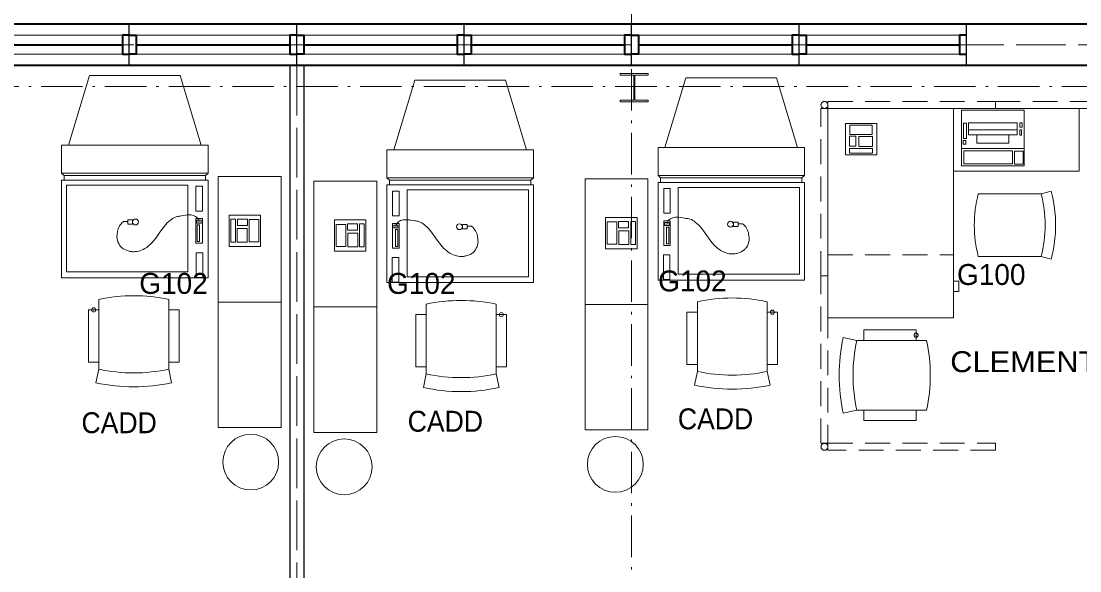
# Model space of a CAD drawing. Extents: x -118748 to -117136, y -118748 to -117596.
# Drawn here: x -118046.3 to -117803.5, y -118079.9 to -117953.8 of the extents above; entities that cross this region are included whole.
import ezdxf
from ezdxf.enums import TextEntityAlignment as Align

# ---------------------------------------------------------------- set-up
doc = ezdxf.new("R2010")
doc.units = 0
doc.header["$LTSCALE"] = 1.9
doc.header["$PDMODE"] = 32
doc.header["$PDSIZE"] = 0.95
for name, pattern in [('DOT_DASHED', [7.7, 5, -1.2, 0.3, -1.2]), ('LONG_DASHED', [7.5, 6, -1.5]), ('MEDIUM_DASHED', [4.5, 3, -1.5])]:
    doc.linetypes.add(name, pattern=pattern)
for name, color, linetype, lineweight in [('10', 7, 'DOT_DASHED', 13), ('12', 7, 'Continuous', 13), ('15', 7, 'Continuous', 13), ('16', 7, 'Continuous', 13), ('20', 7, 'MEDIUM_DASHED', 13), ('23', 7, 'Continuous', 25), ('3', 7, 'Continuous', 35), ('30', 7, 'Continuous', 13), ('4', 7, 'Continuous', 35), ('5', 7, 'Continuous', 13), ('6', 7, 'Continuous', 13), ('60', 7, 'LONG_DASHED', 13), ('9', 7, 'Continuous', 35)]:
    doc.layers.add(name, color=color, linetype=linetype, lineweight=lineweight)
doc.layers.add('53', color=7, linetype='Continuous')

msp = doc.modelspace()

# ---------------------------------------------------------------- linework, layer by layer
at = {"layer": '10'}
for p, q in [((-117906.321, -117628.339), (-117906.321, -118698.41)), ((-118641.571, -117968.81), (-117285.521, -117968.81))]:
    msp.add_line(p, q, dxfattribs=at)
at = {"layer": '12'}
msp.add_lwpolyline([(-117908.916, -117972.298), (-117902.5, -117972.298), (-117902.5, -117971.902), (-117905.584, -117971.902), (-117905.584, -117966.198), (-117902.5, -117966.198), (-117902.5, -117965.802), (-117908.916, -117965.802), (-117908.916, -117966.198), (-117905.832, -117966.198), (-117905.832, -117971.902), (-117908.916, -117971.902)], close=True, dxfattribs=at)
at = {"layer": '15', "lineweight": 25}
for p, q in [((-118021.521, -117964.01), (-118021.521, -117954.41)), ((-118021.521, -117964.01), (-118021.521, -117954.41)), ((-117983.121, -117964.01), (-117983.121, -117954.41)), ((-117983.121, -117964.01), (-117983.121, -117954.41)), ((-117944.721, -117964.01), (-117944.721, -117954.41)), ((-117944.721, -117964.01), (-117944.721, -117954.41)), ((-117906.321, -117964.01), (-117906.321, -117954.41)), ((-117906.321, -117964.01), (-117906.321, -117954.41)), ((-117867.921, -117964.01), (-117867.921, -117954.41)), ((-117867.921, -117964.01), (-117867.921, -117954.41)), ((-117829.521, -117964.01), (-117829.521, -117954.41)), ((-117459.921, -117954.41), (-117829.521, -117954.41)), ((-117469.521, -117964.01), (-117829.521, -117964.01))]:
    msp.add_line(p, q, dxfattribs=at)
at = {"layer": '15'}
for p, q in [((-117826.798, -117993.398), (-117812.398, -117993.398)), ((-117812.398, -117993.398), (-117810.076, -117992.791)), ((-117812.398, -118007.798), (-117826.798, -118007.798)), ((-117812.398, -118007.798), (-117810.076, -118008.404)), ((-118028.49, -118017.64), (-118028.49, -118033.64)), ((-118012.49, -118017.64), (-118012.49, -118033.64)), ((-117953.407, -118018.726), (-117953.407, -118034.726)), ((-117937.407, -118018.726), (-117937.407, -118034.726)), ((-117891.231, -118018.16), (-117891.231, -118034.16)), ((-117875.231, -118018.16), (-117875.231, -118034.16)), ((-118030.89, -118020.04), (-118030.89, -118032.04)), ((-118028.49, -118020.04), (-118030.89, -118020.04)), ((-118028.49, -118020.04), (-118028.49, -118032.04)), ((-118012.49, -118020.04), (-118012.49, -118032.04)), ((-118010.09, -118020.04), (-118012.49, -118020.04)), ((-118010.09, -118020.04), (-118010.09, -118032.04)), ((-117955.807, -118021.126), (-117955.807, -118033.126)), ((-117955.807, -118021.126), (-117953.407, -118021.126)), ((-117953.407, -118021.126), (-117953.407, -118033.126)), ((-117937.407, -118021.126), (-117937.407, -118033.126)), ((-117937.407, -118021.126), (-117935.007, -118021.126)), ((-117935.007, -118021.126), (-117935.007, -118033.126)), ((-117893.631, -118020.56), (-117893.631, -118032.56)), ((-117893.631, -118020.56), (-117891.231, -118020.56)), ((-117891.231, -118020.56), (-117891.231, -118032.56)), ((-117875.231, -118020.56), (-117875.231, -118032.56)), ((-117875.231, -118020.56), (-117872.831, -118020.56)), ((-117872.831, -118020.56), (-117872.831, -118032.56)), ((-117841.071, -118024.64), (-117853.071, -118024.64)), ((-117853.071, -118024.64), (-117853.071, -118027.04)), ((-117841.071, -118027.04), (-117841.071, -118024.64)), ((-117854.671, -118027.04), (-117857.799, -118026.364)), ((-117838.671, -118027.04), (-117854.671, -118027.04)), ((-117841.071, -118027.04), (-117853.071, -118027.04)), ((-118030.89, -118032.04), (-118028.49, -118032.04)), ((-118028.49, -118033.64), (-118029.166, -118036.768)), ((-118012.49, -118032.04), (-118010.09, -118032.04)), ((-118012.49, -118033.64), (-118011.814, -118036.768)), ((-117953.407, -118033.126), (-117955.807, -118033.126)), ((-117935.007, -118033.126), (-117937.407, -118033.126)), ((-117891.231, -118032.56), (-117893.631, -118032.56)), ((-117872.831, -118032.56), (-117875.231, -118032.56)), ((-117953.407, -118034.726), (-117954.084, -118037.853)), ((-117937.407, -118034.726), (-117936.731, -118037.853)), ((-117891.231, -118034.16), (-117891.907, -118037.288)), ((-117875.231, -118034.16), (-117874.555, -118037.288)), ((-117854.671, -118043.04), (-117857.799, -118043.716)), ((-117838.671, -118043.04), (-117854.671, -118043.04)), ((-117841.071, -118043.04), (-117853.071, -118043.04)), ((-117853.071, -118043.04), (-117853.071, -118045.44)), ((-117841.071, -118045.44), (-117841.071, -118043.04)), ((-117841.071, -118045.44), (-117853.071, -118045.44))]:
    msp.add_line(p, q, dxfattribs=at)
for points in [[(-117861.285, -118021.839), (-117832.485, -118021.839), (-117832.485, -117973.839), (-117861.285, -117973.839)], [(-117832.485, -117988.239), (-117803.685, -117988.239), (-117803.685, -117973.839), (-117832.485, -117973.839)], [(-118001.13, -117989.452), (-118001.13, -118018.252), (-117986.73, -118018.252), (-117986.73, -117989.452)], [(-117964.767, -117990.537), (-117964.767, -118019.337), (-117979.167, -118019.337), (-117979.167, -117990.537)], [(-117902.59, -117989.972), (-117902.59, -118018.772), (-117916.99, -118018.772), (-117916.99, -117989.972)], [(-118001.13, -118018.252), (-118001.13, -118047.052), (-117986.73, -118047.052), (-117986.73, -118018.252)], [(-117902.59, -118018.772), (-117902.59, -118047.572), (-117916.99, -118047.572), (-117916.99, -118018.772)], [(-117964.767, -118019.337), (-117964.767, -118048.137), (-117979.167, -118048.137), (-117979.167, -118019.337)]]:
    msp.add_lwpolyline(points, close=True, dxfattribs=at)
for centre, radius, start, end in [((-117799.248, -118000.597), 28.475, 165.35367, 194.64632), ((-117839.948, -118000.597), 28.475, 345.35367, 14.64632), ((-117839.948, -118000.597), 30.875, 345.35367, 14.64632), ((-118020.49, -118054.649), 37.863, 77.80217, 102.19783), ((-117945.407, -118055.734), 37.863, 77.80217, 102.19782), ((-117883.231, -118055.169), 37.863, 77.80217, 102.19782), ((-117817.663, -118035.04), 41.063, 167.80217, 192.19782), ((-117817.663, -118035.04), 37.863, 167.80217, 192.19782), ((-117817.663, -118035.04), 37.863, 167.80217, 192.19782), ((-117875.679, -118035.04), 37.863, 347.80217, 12.19783), ((-118020.49, -117996.632), 37.863, 257.80217, 282.19783), ((-118020.49, -117996.632), 37.863, 257.80217, 282.19783), ((-117945.407, -117997.717), 37.863, 257.80217, 282.19783), ((-117945.407, -117997.717), 37.863, 257.80217, 282.19783), ((-117883.231, -117997.152), 37.863, 257.80217, 282.19783), ((-117883.231, -117997.152), 37.863, 257.80217, 282.19783), ((-118020.49, -117996.632), 41.063, 257.80217, 282.19783), ((-117945.407, -117997.717), 41.063, 257.80217, 282.19783), ((-117883.231, -117997.152), 41.063, 257.80217, 282.19783)]:
    msp.add_arc(centre, radius, start, end, dxfattribs=at)
for p in [(-118029.69, -118020.04), (-117936.207, -118021.126), (-117874.031, -118020.56), (-117841.071, -118025.84)]:
    msp.add_point(p, dxfattribs=at)
at = {"layer": '16'}
for p, q in [((-118059.921, -117954.41), (-118021.521, -117954.41)), ((-118021.521, -117954.41), (-117983.121, -117954.41)), ((-117983.121, -117954.41), (-117944.721, -117954.41)), ((-117944.721, -117954.41), (-117906.321, -117954.41)), ((-117906.321, -117954.41), (-117867.921, -117954.41)), ((-117867.921, -117954.41), (-117829.521, -117954.41)), ((-118058.321, -117957.027), (-118023.121, -117957.027)), ((-118019.921, -117957.027), (-117984.721, -117957.027)), ((-117981.521, -117957.027), (-117946.321, -117957.027)), ((-117943.121, -117957.027), (-117907.921, -117957.027)), ((-117904.721, -117957.027), (-117869.521, -117957.027)), ((-117866.321, -117957.027), (-117831.121, -117957.027)), ((-118023.121, -117961.391), (-118058.321, -117961.391)), ((-117984.721, -117961.391), (-118019.921, -117961.391)), ((-117946.321, -117961.391), (-117981.521, -117961.391)), ((-117907.921, -117961.391), (-117943.121, -117961.391)), ((-117869.521, -117961.391), (-117904.721, -117961.391)), ((-117831.121, -117961.391), (-117866.321, -117961.391)), ((-118021.521, -117964.01), (-118059.921, -117964.01)), ((-117983.121, -117964.01), (-118021.521, -117964.01)), ((-117944.721, -117964.01), (-117983.121, -117964.01)), ((-117906.321, -117964.01), (-117944.721, -117964.01)), ((-117867.921, -117964.01), (-117906.321, -117964.01)), ((-117829.521, -117964.01), (-117867.921, -117964.01)), ((-118035.457, -117982.266), (-118030.657, -117966.266)), ((-118030.657, -117966.266), (-118009.857, -117966.266)), ((-118005.057, -117982.266), (-118009.857, -117966.266)), ((-117960.84, -117983.351), (-117956.04, -117967.351)), ((-117935.24, -117967.351), (-117956.04, -117967.351)), ((-117930.44, -117983.351), (-117935.24, -117967.351)), ((-117898.664, -117982.786), (-117893.864, -117966.786)), ((-117873.064, -117966.786), (-117893.864, -117966.786)), ((-117868.264, -117982.786), (-117873.064, -117966.786)), ((-117830.687, -117983.025), (-117816.287, -117983.025)), ((-118036.474, -117989.2), (-118037.057, -117988.666)), ((-118004.021, -117989.2), (-118003.457, -117988.666)), ((-117961.876, -117990.285), (-117962.44, -117989.751)), ((-117929.423, -117990.285), (-117928.84, -117989.751)), ((-117899.699, -117989.72), (-117900.264, -117989.186)), ((-117867.246, -117989.72), (-117866.664, -117989.186))]:
    msp.add_line(p, q, dxfattribs=at)
at = {"layer": '16', "lineweight": 35}
for p, q in [((-118058.321, -117959.209), (-118023.121, -117959.209)), ((-118019.921, -117959.209), (-117984.721, -117959.209)), ((-117981.521, -117959.209), (-117946.321, -117959.209)), ((-117943.121, -117959.209), (-117907.921, -117959.209)), ((-117904.721, -117959.209), (-117869.521, -117959.209)), ((-117866.321, -117959.209), (-117831.121, -117959.209))]:
    msp.add_line(p, q, dxfattribs=at)
for points in [[(-118021.521, -117957.027), (-118023.121, -117957.027), (-118023.121, -117961.391), (-118021.521, -117961.391)], [(-118021.521, -117957.027), (-118019.921, -117957.027), (-118019.921, -117961.391), (-118021.521, -117961.391)], [(-117983.121, -117957.027), (-117984.721, -117957.027), (-117984.721, -117961.391), (-117983.121, -117961.391)], [(-117983.121, -117957.027), (-117981.521, -117957.027), (-117981.521, -117961.391), (-117983.121, -117961.391)], [(-117944.721, -117957.027), (-117946.321, -117957.027), (-117946.321, -117961.391), (-117944.721, -117961.391)], [(-117944.721, -117957.027), (-117943.121, -117957.027), (-117943.121, -117961.391), (-117944.721, -117961.391)], [(-117906.321, -117957.027), (-117907.921, -117957.027), (-117907.921, -117961.391), (-117906.321, -117961.391)], [(-117906.321, -117957.027), (-117904.721, -117957.027), (-117904.721, -117961.391), (-117906.321, -117961.391)], [(-117867.921, -117957.027), (-117869.521, -117957.027), (-117869.521, -117961.391), (-117867.921, -117961.391)], [(-117867.921, -117957.027), (-117866.321, -117957.027), (-117866.321, -117961.391), (-117867.921, -117961.391)], [(-117829.521, -117957.027), (-117831.121, -117957.027), (-117831.121, -117961.391), (-117829.521, -117961.391)]]:
    msp.add_lwpolyline(points, dxfattribs=at)
at = {"layer": '16'}
for points in [[(-117830.687, -117987.025), (-117830.687, -117974.225), (-117816.287, -117974.225), (-117816.287, -117987.025)], [(-117850.1, -117984.461), (-117857.3, -117984.461), (-117857.3, -117977.261), (-117850.1, -117977.261)], [(-117856.265, -117979.842), (-117851.148, -117979.842), (-117851.148, -117977.637), (-117856.265, -117977.637)], [(-117830.23, -117980.742), (-117830.23, -117977.206), (-117829.522, -117977.206), (-117829.522, -117980.742)], [(-117829.023, -117978.704), (-117829.023, -117977.104), (-117817.914, -117977.104), (-117817.914, -117978.704)], [(-117817.29, -117977.123), (-117817.29, -117978.121), (-117816.707, -117978.121), (-117816.707, -117977.123)], [(-117856.349, -117982.505), (-117854.892, -117982.505), (-117854.892, -117980.216), (-117856.349, -117980.216)], [(-117829.023, -117979.91), (-117829.023, -117978.704), (-117817.914, -117978.704), (-117817.914, -117979.91)], [(-117827.109, -117981.783), (-117827.109, -117979.91), (-117819.786, -117979.91), (-117819.786, -117981.783)], [(-117817.29, -117978.704), (-117817.29, -117979.952), (-117816.874, -117979.952), (-117816.874, -117978.704)], [(-118037.057, -117988.666), (-118037.057, -117982.266), (-118003.457, -117982.266), (-118003.457, -117988.666)], [(-117854.227, -117982.588), (-117851.106, -117982.588), (-117851.106, -117980.299), (-117854.227, -117980.299)], [(-117830.313, -117981.99), (-117830.313, -117981.158), (-117829.647, -117981.158), (-117829.647, -117981.99)], [(-117928.84, -117989.751), (-117928.84, -117983.351), (-117962.44, -117983.351), (-117962.44, -117989.751)], [(-117866.664, -117989.186), (-117866.664, -117982.786), (-117900.264, -117982.786), (-117900.264, -117989.186)], [(-117851.106, -117983.004), (-117856.349, -117983.004), (-117856.349, -117984.086), (-117851.106, -117984.086)], [(-117830.146, -117983.572), (-117830.146, -117986.567), (-117818.954, -117986.567), (-117818.954, -117983.572)], [(-117818.538, -117983.655), (-117818.538, -117986.609), (-117816.541, -117986.609), (-117816.541, -117983.655)], [(-118036.474, -117990.266), (-118036.474, -117989.2), (-118004.021, -117989.2), (-118004.021, -117990.266)], [(-117867.246, -117990.786), (-117867.246, -117989.72), (-117899.699, -117989.72), (-117899.699, -117990.786)], [(-118037.057, -118012.666), (-118037.057, -117990.266), (-118003.457, -117990.266), (-118003.457, -118012.666)], [(-118035.892, -118011.335), (-118035.892, -117991.447), (-118008.098, -117991.447), (-118008.098, -118011.335)], [(-118006.268, -117991.696), (-118006.268, -117997.355), (-118004.77, -117997.355), (-118004.77, -117991.696)], [(-117928.84, -118013.751), (-117928.84, -117991.351), (-117962.44, -117991.351), (-117962.44, -118013.751)], [(-117929.423, -117991.351), (-117929.423, -117990.285), (-117961.876, -117990.285), (-117961.876, -117991.351)], [(-117866.664, -118013.186), (-117866.664, -117990.786), (-117900.264, -117990.786), (-117900.264, -118013.186)], [(-117897.453, -117992.216), (-117897.453, -117997.875), (-117898.951, -117997.875), (-117898.951, -117992.216)], [(-117867.829, -118011.855), (-117867.829, -117991.967), (-117895.622, -117991.967), (-117895.622, -118011.855)], [(-117959.629, -117992.781), (-117959.629, -117998.44), (-117961.127, -117998.44), (-117961.127, -117992.781)], [(-117930.005, -118012.42), (-117930.005, -117992.532), (-117957.799, -117992.532), (-117957.799, -118012.42)], [(-118021.876, -117999.372), (-118021.876, -118000.37), (-118020.794, -118000.37), (-118020.794, -117999.372)], [(-118006.268, -117999.102), (-118006.268, -118004.761), (-118004.77, -118004.761), (-118004.77, -117999.102)], [(-118005.999, -117999.485), (-118005.999, -118000.152), (-118005.015, -118000.152), (-118005.015, -117999.485)], [(-117998.643, -118005.496), (-117998.643, -117998.296), (-117991.443, -117998.296), (-117991.443, -118005.496)], [(-117997.186, -118004.489), (-117997.186, -117999.247), (-117998.268, -117999.247), (-117998.268, -118004.489)], [(-117996.687, -117999.247), (-117996.687, -118000.703), (-117994.399, -118000.703), (-117994.399, -117999.247)], [(-117994.024, -117999.33), (-117994.024, -118004.448), (-117991.819, -118004.448), (-117991.819, -117999.33)], [(-117967.254, -118006.581), (-117967.254, -117999.381), (-117974.454, -117999.381), (-117974.454, -118006.581)], [(-117905.077, -118006.016), (-117905.077, -117998.816), (-117912.277, -117998.816), (-117912.277, -118006.016)], [(-117897.453, -117999.622), (-117897.453, -118005.281), (-117898.951, -118005.281), (-117898.951, -117999.622)], [(-118005.936, -118000.533), (-118005.936, -118004.375), (-118005.428, -118004.375), (-118005.428, -118000.533)], [(-117996.77, -118001.369), (-117996.77, -118004.489), (-117994.482, -118004.489), (-117994.482, -118001.369)], [(-117971.873, -118000.415), (-117971.873, -118005.533), (-117974.078, -118005.533), (-117974.078, -118000.415)], [(-117969.21, -118000.332), (-117969.21, -118001.788), (-117971.498, -118001.788), (-117971.498, -118000.332)], [(-117968.711, -118005.574), (-117968.711, -118000.332), (-117967.629, -118000.332), (-117967.629, -118005.574)], [(-117959.629, -118000.187), (-117959.629, -118005.846), (-117961.127, -118005.846), (-117961.127, -118000.187)], [(-117959.898, -118000.571), (-117959.898, -118001.237), (-117960.882, -118001.237), (-117960.882, -118000.571)], [(-117959.962, -118001.618), (-117959.962, -118005.46), (-117960.47, -118005.46), (-117960.47, -118001.618)], [(-117944.021, -118000.457), (-117944.021, -118001.455), (-117945.103, -118001.455), (-117945.103, -118000.457)], [(-117909.696, -117999.85), (-117909.696, -118004.968), (-117911.901, -118004.968), (-117911.901, -117999.85)], [(-117907.033, -117999.767), (-117907.033, -118001.223), (-117909.322, -118001.223), (-117909.322, -117999.767)], [(-117906.95, -118001.889), (-117906.95, -118005.009), (-117909.238, -118005.009), (-117909.238, -118001.889)], [(-117906.534, -118005.009), (-117906.534, -117999.767), (-117905.452, -117999.767), (-117905.452, -118005.009)], [(-117897.721, -118000.005), (-117897.721, -118000.672), (-117898.706, -118000.672), (-117898.706, -118000.005)], [(-117897.785, -118001.053), (-117897.785, -118004.895), (-117898.293, -118004.895), (-117898.293, -118001.053)], [(-117881.844, -117999.892), (-117881.844, -118000.89), (-117882.926, -118000.89), (-117882.926, -117999.892)], [(-117969.127, -118002.454), (-117969.127, -118005.574), (-117971.415, -118005.574), (-117971.415, -118002.454)], [(-118006.185, -118006.924), (-118006.185, -118012.583), (-118004.687, -118012.583), (-118004.687, -118006.924)], [(-117959.713, -118008.009), (-117959.713, -118013.668), (-117961.211, -118013.668), (-117961.211, -118008.009)], [(-117897.536, -118007.444), (-117897.536, -118013.103), (-117899.034, -118013.103), (-117899.034, -118007.444)]]:
    msp.add_lwpolyline(points, close=True, dxfattribs=at)
for centre in [(-118020.093, -117999.875), (-117945.804, -118000.96), (-117883.627, -118000.395)]:
    msp.add_circle(centre, 0.671, dxfattribs=at)
for points in [[(-118005.519, -117999.934), (-118005.602, -117999.435), (-118006.351, -117998.603), (-118007.433, -117998.27), (-118009.846, -117998.52), (-118010.761, -117998.686), (-118012.093, -117999.435), (-118017.169, -118005.426), (-118018.75, -118006.342), (-118020.164, -118006.675), (-118020.997, -118006.675), (-118021.745, -118006.508), (-118023.243, -118005.759), (-118023.743, -118005.177), (-118024.325, -118003.679), (-118024.242, -118002.181), (-118024.075, -118001.432), (-118023.327, -118000.184), (-118022.827, -117999.768), (-118022.162, -117999.768), (-118021.995, -117999.768), (-118021.912, -117999.851)], [(-117960.378, -118001.02), (-117960.295, -118000.52), (-117959.546, -117999.688), (-117958.465, -117999.355), (-117956.051, -117999.605), (-117955.136, -117999.771), (-117953.805, -118000.52), (-117948.728, -118006.512), (-117947.147, -118007.427), (-117945.733, -118007.76), (-117944.901, -118007.76), (-117944.152, -118007.593), (-117942.654, -118006.844), (-117942.155, -118006.262), (-117941.572, -118004.764), (-117941.655, -118003.266), (-117941.822, -118002.517), (-117942.571, -118001.269), (-117943.07, -118000.853), (-117943.736, -118000.853), (-117943.902, -118000.853), (-117943.985, -118000.936)], [(-117898.202, -118000.454), (-117898.118, -117999.955), (-117897.369, -117999.123), (-117896.288, -117998.79), (-117893.875, -117999.04), (-117892.959, -117999.206), (-117891.628, -117999.955), (-117886.552, -118005.946), (-117884.971, -118006.862), (-117883.556, -118007.195), (-117882.724, -118007.195), (-117881.975, -118007.028), (-117880.477, -118006.279), (-117879.978, -118005.697), (-117879.395, -118004.199), (-117879.479, -118002.701), (-117879.645, -118001.952), (-117880.394, -118000.704), (-117880.893, -118000.288), (-117881.559, -118000.288), (-117881.725, -118000.288), (-117881.808, -118000.371)]]:
    msp.add_spline(points, degree=3, dxfattribs=at)
at = {"layer": '20'}
for points in [[(-117861.285, -117973.839), (-117861.285, -117972.239), (-117822.885, -117972.239), (-117822.885, -117973.839)], [(-117822.885, -117973.839), (-117822.885, -117972.239), (-117784.485, -117972.239), (-117784.485, -117973.839)], [(-117862.885, -117973.839), (-117861.285, -117973.839), (-117861.285, -118012.239), (-117862.885, -118012.239)], [(-117862.885, -118012.239), (-117861.285, -118012.239), (-117861.285, -118050.639), (-117862.885, -118050.639)], [(-117861.285, -118052.239), (-117861.285, -118050.639), (-117822.885, -118050.639), (-117822.885, -118052.239)]]:
    msp.add_lwpolyline(points, close=True, dxfattribs=at)
for centre in [(-117862.085, -117973.039), (-117862.085, -118051.439)]:
    msp.add_circle(centre, 0.8, dxfattribs=at)
at = {"layer": '23'}
for p, q in [((-117981.521, -117964.01), (-117984.721, -117964.01)), ((-117984.721, -117964.01), (-117984.721, -118118.36)), ((-117981.521, -117964.01), (-117981.521, -118118.36))]:
    msp.add_line(p, q, dxfattribs=at)
at = {"layer": '23', "linetype": 'MEDIUM_DASHED', "lineweight": 13}
for points in [[(-117832.485, -118021.839), (-117861.285, -118021.839), (-117861.285, -118007.439), (-117832.485, -118007.439)], [(-117832.485, -118015.839), (-117831.285, -118015.839), (-117831.285, -118013.439), (-117832.485, -118013.439)]]:
    msp.add_lwpolyline(points, close=True, dxfattribs=at)
at = {"layer": '3'}
msp.add_lwpolyline([(-118098.321, -117954.41), (-117829.521, -117954.41), (-117459.921, -117954.41), (-117459.921, -118170.41), (-117370.321, -118170.41), (-117370.321, -118352.81), (-117459.921, -118352.81), (-117459.921, -118645.61), (-117704.721, -118645.61), (-117704.721, -118592.81), (-117847.121, -118592.81), (-117850.321, -118592.801), (-117860.744, -118590.984), (-117862.249, -118590.443), (-117871.571, -118585.668), (-117872.847, -118584.703), (-117880.323, -118577.368), (-117881.254, -118576.067), (-117886.205, -118566.837), (-117886.706, -118565.318), (-117888.682, -118555.032), (-117888.707, -118553.433), (-117890.316, -118553.433)], dxfattribs=at)
at = {"layer": '30'}
for centre in [(-117993.669, -118054.948), (-117972.228, -118056.034), (-117910.052, -118055.469)]:
    msp.add_circle(centre, 6.4, dxfattribs=at)
at = {"layer": '4'}
msp.add_lwpolyline([(-118496.721, -117964.01), (-118496.721, -118636.01), (-118271.121, -118636.01), (-118271.121, -118588.01), (-118115.969, -118588.01), (-118106.1, -118586.234), (-118096.66, -118581.314), (-118089.115, -118573.804), (-118084.156, -118564.399), (-118081.154, -118548.633), (-118079.134, -118548.633), (-117884.057, -118548.587), (-117881.646, -118565.336), (-117876.897, -118574.111), (-117869.271, -118581.538), (-117859.789, -118586.351), (-117850.271, -118588.01), (-117695.121, -118588.01), (-117695.121, -118636.01), (-117469.521, -118636.01), (-117469.521, -117964.01)], close=True, dxfattribs=at)
at = {"layer": '5'}
msp.add_line((-118496.721, -117964.01), (-117986.969, -117964.01), dxfattribs=at)
for points in [[(-118496.721, -117964.01), (-118098.321, -117964.01), (-117984.721, -117964.01), (-117984.721, -118118.36), (-118059.921, -118118.36)], [(-117981.521, -118118.36), (-117981.521, -117964.01), (-117469.521, -117964.01), (-117469.521, -117992.81), (-117469.521, -118180.01), (-117469.521, -118292.01), (-117839.871, -118292.01), (-117839.871, -118184.81)], [(-117979.078, -117964.01), (-117469.521, -117964.01), (-117469.521, -118636.01), (-117695.121, -118636.01), (-117695.121, -118588.01), (-117850.271, -118588.01)]]:
    msp.add_lwpolyline(points, dxfattribs=at)
at = {"layer": '6'}
for points in [[(-118496.721, -117964.01), (-117984.721, -117964.01), (-117984.721, -118118.36), (-118059.921, -118118.36)], [(-117981.521, -117964.01), (-117469.521, -117964.01), (-117469.521, -118292.01), (-117839.871, -118292.01), (-117839.871, -118184.81)], [(-117906.321, -118118.36), (-117981.521, -118118.36), (-117981.521, -117964.01)]]:
    msp.add_lwpolyline(points, dxfattribs=at)
at = {"layer": '60'}
msp.add_line((-117983.121, -117964.01), (-117983.121, -118119.96), dxfattribs=at)
msp.add_lwpolyline([(-117464.721, -118175.21), (-117464.721, -117959.21), (-118501.521, -117959.21)], dxfattribs=at)

# ---------------------------------------------------------------- texts
at = {"layer": '53'}
for s, width, p in [('CLEMENTS,T.', 1.1, (-117833.238, -118034.323)), ('CADD', 0.95, (-117957.673, -118047.987)), ('CADD', 0.95, (-117895.704, -118047.439)), ('CADD', 0.95, (-118032.491, -118048.322))]:
    msp.add_text(s, height=4.8, dxfattribs=dict(at, width=width)).set_placement(p)
at = {"layer": '9'}
for s, p in [('G102', (-118011.38, -118016.367)), ('G102', (-117954.554, -118016.367)), ('G102', (-117892.378, -118015.802)), ('G100', (-117823.832, -118014.325))]:
    msp.add_text(s, height=4.8, dxfattribs=at).set_placement(p, align=Align.CENTER)

doc.saveas('drawing.dxf')
